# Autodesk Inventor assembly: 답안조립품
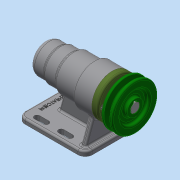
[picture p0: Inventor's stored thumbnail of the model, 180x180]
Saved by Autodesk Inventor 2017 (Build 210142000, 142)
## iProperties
Part Number: 답안조립품
Material: 일반
Document SubType Name: Assembly
Designer: MRC
Author: MRC
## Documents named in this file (12)
- C:\Users\MRC\Desktop\711009V1010\답안조립품.iam
- C:\Users\MRC\Desktop\711009V1010\본체.ipt
- C:\Users\MRC\Desktop\711009V1010\V벨트풀리.ipt
- C:\Users\MRC\Desktop\711009V1010\멈춤나사 M3.ipt
- C:\Users\MRC\Desktop\711009V1010\베어링 6004.ipt
- C:\Users\MRC\Desktop\711009V1010\베어링 51202.ipt
- C:\Users\MRC\Desktop\711009V1010\볼트 M4.ipt
- C:\Users\MRC\Desktop\711009V1010\어댑터슬리브.ipt
- C:\Users\MRC\Desktop\711009V1010\오일 실 20x35x7.ipt
- C:\Users\MRC\Desktop\711009V1010\축.ipt
- C:\Users\MRC\Desktop\711009V1010\커버.ipt
- C:\Users\MRC\Desktop\711009V1010\키 5x5.ipt
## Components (1 placed, 1 different names)
1. V벨트풀리:1
